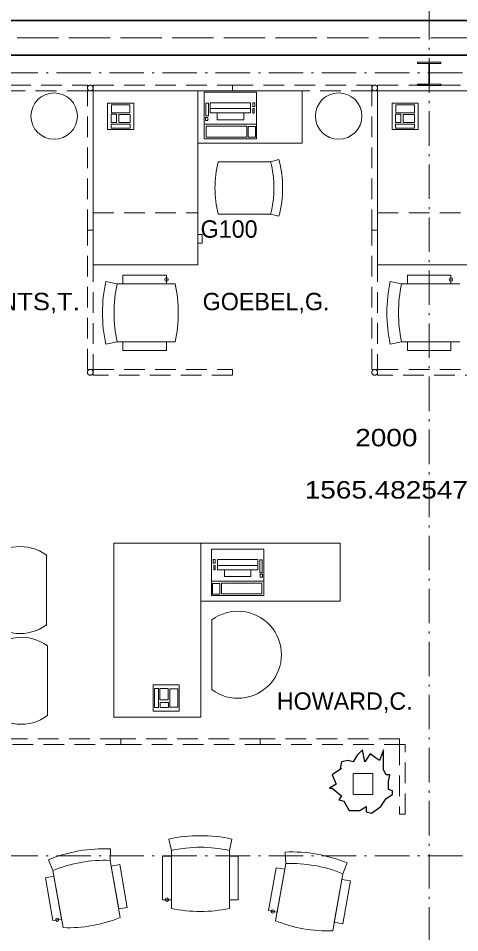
# Model space of a CAD drawing. Extents: x -118748 to -117136, y -118748 to -117596.
# Drawn here: x -117803.5 to -117681.9, y -118206 to -117953.8 of the extents above; entities that cross this region are included whole.
import ezdxf
from ezdxf.enums import TextEntityAlignment as Align

# ---------------------------------------------------------------- set-up
doc = ezdxf.new("R2010")
doc.units = 0
doc.header["$LTSCALE"] = 1.9
doc.header["$PDMODE"] = 32
doc.header["$PDSIZE"] = 0.95
for name, pattern in [('DOT_DASHED', [7.7, 5, -1.2, 0.3, -1.2]), ('LONG_DASHED', [7.5, 6, -1.5]), ('MEDIUM_DASHED', [4.5, 3, -1.5])]:
    doc.linetypes.add(name, pattern=pattern)
for name, color, linetype, lineweight in [('10', 7, 'DOT_DASHED', 13), ('12', 7, 'Continuous', 13), ('15', 7, 'Continuous', 13), ('16', 7, 'Continuous', 13), ('17', 7, 'Continuous', 25), ('20', 7, 'MEDIUM_DASHED', 13), ('23', 7, 'Continuous', 25), ('3', 7, 'Continuous', 35), ('30', 7, 'Continuous', 13), ('4', 7, 'Continuous', 35), ('45', 7, 'Continuous', 25), ('5', 7, 'Continuous', 13), ('6', 7, 'Continuous', 13), ('60', 7, 'LONG_DASHED', 13), ('9', 7, 'Continuous', 35)]:
    doc.layers.add(name, color=color, linetype=linetype, lineweight=lineweight)
doc.layers.add('53', color=7, linetype='Continuous')

msp = doc.modelspace()

# ---------------------------------------------------------------- linework, layer by layer
at = {"layer": '10'}
for p, q in [((-117690.321, -117628.339), (-117690.321, -118698.41)), ((-118641.571, -117968.81), (-117285.521, -117968.81)), ((-118641.571, -118184.81), (-117285.521, -118184.81))]:
    msp.add_line(p, q, dxfattribs=at)
at = {"layer": '12'}
msp.add_lwpolyline([(-117693.504, -117972.362), (-117687.088, -117972.362), (-117687.088, -117971.966), (-117690.172, -117971.966), (-117690.172, -117966.262), (-117687.088, -117966.262), (-117687.088, -117965.866), (-117693.504, -117965.866), (-117693.504, -117966.262), (-117690.42, -117966.262), (-117690.42, -117971.966), (-117693.504, -117971.966)], close=True, dxfattribs=at)
at = {"layer": '15', "lineweight": 25}
for p, q in [((-117459.921, -117954.41), (-117829.521, -117954.41)), ((-117469.521, -117964.01), (-117829.521, -117964.01))]:
    msp.add_line(p, q, dxfattribs=at)
at = {"layer": '15'}
for p, q in [((-117733.998, -117993.398), (-117731.676, -117992.791)), ((-117748.398, -117993.398), (-117733.998, -117993.398)), ((-117733.998, -118007.798), (-117748.398, -118007.798)), ((-117733.998, -118007.798), (-117731.676, -118008.404)), ((-117762.671, -118024.64), (-117774.671, -118024.64)), ((-117774.671, -118024.64), (-117774.671, -118027.04)), ((-117762.671, -118027.04), (-117762.671, -118024.64)), ((-117684.271, -118024.64), (-117696.271, -118024.64)), ((-117696.271, -118024.64), (-117696.271, -118027.04)), ((-117684.271, -118027.04), (-117684.271, -118024.64)), ((-117776.271, -118027.04), (-117779.399, -118026.364)), ((-117760.271, -118027.04), (-117776.271, -118027.04)), ((-117762.671, -118027.04), (-117774.671, -118027.04)), ((-117697.871, -118027.04), (-117700.999, -118026.364)), ((-117681.871, -118027.04), (-117697.871, -118027.04)), ((-117684.271, -118027.04), (-117696.271, -118027.04)), ((-117776.271, -118043.04), (-117779.399, -118043.716)), ((-117760.271, -118043.04), (-117776.271, -118043.04)), ((-117762.671, -118043.04), (-117774.671, -118043.04)), ((-117774.671, -118043.04), (-117774.671, -118045.44)), ((-117762.671, -118045.44), (-117762.671, -118043.04)), ((-117697.871, -118043.04), (-117700.999, -118043.716)), ((-117681.871, -118043.04), (-117697.871, -118043.04)), ((-117684.271, -118043.04), (-117696.271, -118043.04)), ((-117696.271, -118043.04), (-117696.271, -118045.44)), ((-117684.271, -118045.44), (-117684.271, -118043.04)), ((-117762.671, -118045.44), (-117774.671, -118045.44)), ((-117684.271, -118045.44), (-117696.271, -118045.44)), ((-117795.772, -118101.88), (-117795.772, -118121.08)), ((-117750.211, -118138.921), (-117750.211, -118119.721)), ((-117795.491, -118126.911), (-117795.491, -118146.111)), ((-117761.333, -118183.276), (-117762.009, -118180.149)), ((-117745.333, -118183.276), (-117744.657, -118180.149)), ((-117778.215, -118186.033), (-117778.092, -118182.835)), ((-117761.333, -118199.276), (-117761.333, -118183.276)), ((-117745.333, -118199.276), (-117745.333, -118183.276)), ((-117729.827, -118186.921), (-117729.95, -118183.724)), ((-117793.972, -118188.811), (-117795.181, -118185.848)), ((-117775.436, -118201.79), (-117778.215, -118186.033)), ((-117777.937, -118187.609), (-117775.573, -118187.192)), ((-117773.49, -118199.01), (-117775.573, -118187.192)), ((-117763.733, -118196.876), (-117763.733, -118184.876)), ((-117763.733, -118184.876), (-117761.333, -118184.876)), ((-117761.333, -118196.876), (-117761.333, -118184.876)), ((-117745.333, -118196.876), (-117745.333, -118184.876)), ((-117745.333, -118184.876), (-117742.933, -118184.876)), ((-117742.933, -118196.876), (-117742.933, -118184.876)), ((-117732.606, -118202.678), (-117729.827, -118186.921)), ((-117714.071, -118189.7), (-117712.861, -118186.737)), ((-117791.193, -118204.568), (-117793.972, -118188.811)), ((-117775.853, -118199.426), (-117777.937, -118187.609)), ((-117734.553, -118199.898), (-117732.469, -118188.08)), ((-117732.469, -118188.08), (-117730.105, -118188.497)), ((-117732.189, -118200.315), (-117730.105, -118188.497)), ((-117716.849, -118205.457), (-117714.071, -118189.7)), ((-117796.057, -118190.804), (-117793.694, -118190.387)), ((-117793.974, -118202.621), (-117796.057, -118190.804)), ((-117791.61, -118202.205), (-117793.694, -118190.387)), ((-117716.432, -118203.093), (-117714.348, -118191.275)), ((-117714.348, -118191.275), (-117711.985, -118191.692)), ((-117714.069, -118203.51), (-117711.985, -118191.692)), ((-117761.333, -118196.876), (-117763.733, -118196.876)), ((-117742.933, -118196.876), (-117745.333, -118196.876)), ((-117773.49, -118199.01), (-117775.853, -118199.426)), ((-117791.61, -118202.205), (-117793.974, -118202.621)), ((-117732.189, -118200.315), (-117734.553, -118199.898)), ((-117714.069, -118203.51), (-117716.432, -118203.093))]:
    msp.add_line(p, q, dxfattribs=at)
for points in [[(-117782.885, -118021.839), (-117754.085, -118021.839), (-117754.085, -117973.839), (-117782.885, -117973.839)], [(-117754.085, -117988.239), (-117725.285, -117988.239), (-117725.285, -117973.839), (-117754.085, -117973.839)], [(-117704.485, -118021.839), (-117675.685, -118021.839), (-117675.685, -117973.839), (-117704.485, -117973.839)], [(-117777.21, -118146.556), (-117777.21, -118098.556), (-117753.21, -118098.556), (-117753.21, -118146.556)], [(-117753.21, -118114.556), (-117753.21, -118098.556), (-117714.81, -118098.556), (-117714.81, -118114.556)]]:
    msp.add_lwpolyline(points, close=True, dxfattribs=at)
for centre, radius, start, end in [((-117761.548, -118000.597), 30.875, 345.35367, 14.64632), ((-117720.848, -118000.597), 28.475, 165.35367, 194.64632), ((-117761.548, -118000.597), 28.475, 345.35367, 14.64632), ((-117739.263, -118035.04), 41.063, 167.80217, 192.19782), ((-117739.263, -118035.04), 37.863, 167.80217, 192.19782), ((-117739.263, -118035.04), 37.863, 167.80217, 192.19782), ((-117797.279, -118035.04), 37.863, 347.80217, 12.19783), ((-117660.863, -118035.04), 41.063, 167.80217, 192.19782), ((-117660.863, -118035.04), 37.863, 167.80217, 192.19782), ((-117660.863, -118035.04), 37.863, 167.80217, 192.19782), ((-117802.972, -118111.48), 12, 53.1301, 306.86989), ((-117743.011, -118129.321), 12, 233.1301, 126.8699), ((-117802.691, -118136.511), 12, 53.1301, 306.86989), ((-117753.333, -118220.285), 41.063, 77.80217, 102.19783), ((-117779.667, -118223.868), 41.063, 87.80217, 112.19783), ((-117753.333, -118220.285), 37.863, 77.80217, 102.19783), ((-117753.333, -118220.285), 37.863, 77.80217, 102.19783), ((-117728.375, -118224.757), 41.063, 67.80217, 92.19783), ((-117779.667, -118223.868), 37.863, 87.80217, 112.19783), ((-117779.667, -118223.868), 37.863, 87.80217, 112.19783), ((-117728.375, -118224.757), 37.863, 67.80217, 92.19783), ((-117728.375, -118224.757), 37.863, 67.80217, 92.19783), ((-117753.333, -118162.268), 37.863, 257.80217, 282.19782), ((-117789.741, -118166.733), 37.863, 267.80217, 292.19783), ((-117718.301, -118167.621), 37.863, 247.80218, 272.19783)]:
    msp.add_arc(centre, radius, start, end, dxfattribs=at)
for p in [(-117762.671, -118025.84), (-117684.271, -118025.84), (-117762.533, -118196.876), (-117733.371, -118200.106), (-117792.792, -118202.413)]:
    msp.add_point(p, dxfattribs=at)
at = {"layer": '16'}
for p, q in [((-117752.287, -117983.025), (-117737.887, -117983.025)), ((-117735.829, -118109.006), (-117750.229, -118109.006))]:
    msp.add_line(p, q, dxfattribs=at)
for points in [[(-117752.287, -117987.025), (-117752.287, -117974.225), (-117737.887, -117974.225), (-117737.887, -117987.025)], [(-117771.7, -117984.461), (-117778.9, -117984.461), (-117778.9, -117977.261), (-117771.7, -117977.261)], [(-117777.865, -117979.842), (-117772.748, -117979.842), (-117772.748, -117977.637), (-117777.865, -117977.637)], [(-117751.83, -117980.742), (-117751.83, -117977.206), (-117751.122, -117977.206), (-117751.122, -117980.742)], [(-117750.623, -117978.704), (-117750.623, -117977.104), (-117739.514, -117977.104), (-117739.514, -117978.704)], [(-117738.89, -117977.123), (-117738.89, -117978.121), (-117738.307, -117978.121), (-117738.307, -117977.123)], [(-117693.3, -117984.461), (-117700.5, -117984.461), (-117700.5, -117977.261), (-117693.3, -117977.261)], [(-117699.465, -117979.842), (-117694.348, -117979.842), (-117694.348, -117977.637), (-117699.465, -117977.637)], [(-117777.948, -117982.505), (-117776.492, -117982.505), (-117776.492, -117980.216), (-117777.948, -117980.216)], [(-117775.827, -117982.588), (-117772.706, -117982.588), (-117772.706, -117980.299), (-117775.827, -117980.299)], [(-117750.623, -117979.91), (-117750.623, -117978.704), (-117739.514, -117978.704), (-117739.514, -117979.91)], [(-117748.709, -117981.783), (-117748.709, -117979.91), (-117741.386, -117979.91), (-117741.386, -117981.783)], [(-117738.89, -117978.704), (-117738.89, -117979.952), (-117738.474, -117979.952), (-117738.474, -117978.704)], [(-117699.549, -117982.505), (-117698.092, -117982.505), (-117698.092, -117980.216), (-117699.549, -117980.216)], [(-117697.427, -117982.588), (-117694.306, -117982.588), (-117694.306, -117980.299), (-117697.427, -117980.299)], [(-117751.913, -117981.99), (-117751.913, -117981.158), (-117751.247, -117981.158), (-117751.247, -117981.99)], [(-117772.706, -117983.004), (-117777.948, -117983.004), (-117777.948, -117984.086), (-117772.706, -117984.086)], [(-117751.746, -117983.572), (-117751.746, -117986.567), (-117740.554, -117986.567), (-117740.554, -117983.572)], [(-117740.138, -117983.655), (-117740.138, -117986.609), (-117738.141, -117986.609), (-117738.141, -117983.655)], [(-117694.306, -117983.004), (-117699.549, -117983.004), (-117699.549, -117984.086), (-117694.306, -117984.086)], [(-117735.829, -118113.006), (-117735.829, -118100.206), (-117750.229, -118100.206), (-117750.229, -118113.006)], [(-117749.227, -118103.104), (-117749.227, -118104.102), (-117749.809, -118104.102), (-117749.809, -118103.104)], [(-117737.494, -118104.685), (-117737.494, -118103.085), (-117748.603, -118103.085), (-117748.603, -118104.685)], [(-117736.287, -118106.724), (-117736.287, -118103.187), (-117736.994, -118103.187), (-117736.994, -118106.724)], [(-117749.227, -118104.685), (-117749.227, -118105.933), (-117749.643, -118105.933), (-117749.643, -118104.685)], [(-117737.494, -118105.891), (-117737.494, -118104.685), (-117748.603, -118104.685), (-117748.603, -118105.891)], [(-117739.408, -118107.764), (-117739.408, -118105.891), (-117746.73, -118105.891), (-117746.73, -118107.764)], [(-117736.204, -118107.972), (-117736.204, -118107.14), (-117736.87, -118107.14), (-117736.87, -118107.972)], [(-117747.979, -118109.636), (-117747.979, -118112.59), (-117749.976, -118112.59), (-117749.976, -118109.636)], [(-117736.37, -118109.553), (-117736.37, -118112.549), (-117747.562, -118112.549), (-117747.562, -118109.553)], [(-117766.352, -118137.661), (-117766.352, -118144.861), (-117759.152, -118144.861), (-117759.152, -118137.661)], [(-117764.896, -118138.667), (-117764.896, -118143.909), (-117765.977, -118143.909), (-117765.977, -118138.667)], [(-117764.48, -118141.787), (-117764.48, -118138.667), (-117762.191, -118138.667), (-117762.191, -118141.787)], [(-117761.734, -118143.826), (-117761.734, -118138.708), (-117759.528, -118138.708), (-117759.528, -118143.826)], [(-117764.396, -118143.909), (-117764.396, -118142.453), (-117762.108, -118142.453), (-117762.108, -118143.909)]]:
    msp.add_lwpolyline(points, close=True, dxfattribs=at)
at = {"layer": '17'}
msp.add_lwpolyline([(-117714.49, -118160.662), (-117717.024, -118162.472), (-117715.938, -118165.006), (-117717.749, -118166.092), (-117717.024, -118166.092), (-117714.49, -118168.264), (-117715.214, -118169.351), (-117713.766, -118169.713), (-117712.318, -118172.247), (-117709.422, -118172.247), (-117707.611, -118171.161), (-117707.611, -118172.609), (-117706.163, -118172.971), (-117703.629, -118171.161), (-117702.181, -118168.989), (-117700.371, -118167.902), (-117700.371, -118166.816), (-117701.457, -118166.454), (-117701.457, -118164.282), (-117701.095, -118162.472), (-117702.181, -118162.472), (-117702.905, -118161.024), (-117702.905, -118155.593), (-117703.991, -118158.489), (-117705.077, -118157.765), (-117706.525, -118156.679), (-117707.974, -118158.851), (-117708.698, -118155.593), (-117710.146, -118157.041), (-117711.232, -118158.851), (-117712.68, -118158.489), (-117714.49, -118158.851), (-117714.852, -118160.662)], dxfattribs=at)
at = {"layer": '17', "lineweight": 13}
msp.add_lwpolyline([(-117711.232, -118162.11), (-117711.232, -118167.902), (-117705.801, -118167.902), (-117705.801, -118162.11)], close=True, dxfattribs=at)
at = {"layer": '20'}
for points in [[(-117822.885, -117973.839), (-117822.885, -117972.239), (-117784.485, -117972.239), (-117784.485, -117973.839)], [(-117782.885, -117973.839), (-117782.885, -117972.239), (-117744.485, -117972.239), (-117744.485, -117973.839)], [(-117744.485, -117973.839), (-117744.485, -117972.239), (-117706.085, -117972.239), (-117706.085, -117973.839)], [(-117704.485, -117973.839), (-117704.485, -117972.239), (-117666.085, -117972.239), (-117666.085, -117973.839)], [(-117784.485, -117973.839), (-117782.885, -117973.839), (-117782.885, -118012.239), (-117784.485, -118012.239)], [(-117784.485, -117973.839), (-117782.885, -117973.839), (-117782.885, -118012.239), (-117784.485, -118012.239)], [(-117706.085, -117973.839), (-117704.485, -117973.839), (-117704.485, -118012.239), (-117706.085, -118012.239)], [(-117706.085, -117973.839), (-117704.485, -117973.839), (-117704.485, -118012.239), (-117706.085, -118012.239)], [(-117784.485, -118012.239), (-117782.885, -118012.239), (-117782.885, -118050.639), (-117784.485, -118050.639)], [(-117784.485, -118012.239), (-117782.885, -118012.239), (-117782.885, -118050.639), (-117784.485, -118050.639)], [(-117706.085, -118012.239), (-117704.485, -118012.239), (-117704.485, -118050.639), (-117706.085, -118050.639)], [(-117706.085, -118012.239), (-117704.485, -118012.239), (-117704.485, -118050.639), (-117706.085, -118050.639)], [(-117782.885, -118052.239), (-117782.885, -118050.639), (-117744.485, -118050.639), (-117744.485, -118052.239)], [(-117704.485, -118052.239), (-117704.485, -118050.639), (-117666.085, -118050.639), (-117666.085, -118052.239)], [(-117813.695, -118152.479), (-117813.695, -118154.079), (-117775.295, -118154.079), (-117775.295, -118152.479)], [(-117775.295, -118152.479), (-117775.295, -118154.079), (-117736.895, -118154.079), (-117736.895, -118152.479)], [(-117736.895, -118152.479), (-117736.895, -118154.079), (-117698.495, -118154.079), (-117698.495, -118152.479)], [(-117696.895, -118154.079), (-117698.495, -118154.079), (-117698.495, -118173.279), (-117696.895, -118173.279)]]:
    msp.add_lwpolyline(points, close=True, dxfattribs=at)
for centre in [(-117783.685, -117973.039), (-117783.685, -117973.039), (-117705.285, -117973.039), (-117705.285, -117973.039), (-117783.685, -118051.439), (-117705.285, -118051.439)]:
    msp.add_circle(centre, 0.8, dxfattribs=at)
at = {"layer": '23', "linetype": 'MEDIUM_DASHED', "lineweight": 13}
for points in [[(-117754.085, -118021.839), (-117782.885, -118021.839), (-117782.885, -118007.439), (-117754.085, -118007.439)], [(-117675.685, -118021.839), (-117704.485, -118021.839), (-117704.485, -118007.439), (-117675.685, -118007.439)], [(-117754.085, -118015.839), (-117752.885, -118015.839), (-117752.885, -118013.439), (-117754.085, -118013.439)]]:
    msp.add_lwpolyline(points, close=True, dxfattribs=at)
at = {"layer": '3'}
msp.add_lwpolyline([(-118098.321, -117954.41), (-117829.521, -117954.41), (-117459.921, -117954.41), (-117459.921, -118170.41), (-117370.321, -118170.41), (-117370.321, -118352.81), (-117459.921, -118352.81), (-117459.921, -118645.61), (-117704.721, -118645.61), (-117704.721, -118592.81), (-117847.121, -118592.81), (-117850.321, -118592.801), (-117860.744, -118590.984), (-117862.249, -118590.443), (-117871.571, -118585.668), (-117872.847, -118584.703), (-117880.323, -118577.368), (-117881.254, -118576.067), (-117886.205, -118566.837), (-117886.706, -118565.318), (-117888.682, -118555.032), (-117888.707, -118553.433), (-117890.316, -118553.433)], dxfattribs=at)
at = {"layer": '30'}
for centre in [(-117793.635, -117980.776), (-117715.235, -117980.776)]:
    msp.add_circle(centre, 6.4, dxfattribs=at)
at = {"layer": '4'}
msp.add_lwpolyline([(-118496.721, -117964.01), (-118496.721, -118636.01), (-118271.121, -118636.01), (-118271.121, -118588.01), (-118115.969, -118588.01), (-118106.1, -118586.234), (-118096.66, -118581.314), (-118089.115, -118573.804), (-118084.156, -118564.399), (-118081.154, -118548.633), (-118079.134, -118548.633), (-117884.057, -118548.587), (-117881.646, -118565.336), (-117876.897, -118574.111), (-117869.271, -118581.538), (-117859.789, -118586.351), (-117850.271, -118588.01), (-117695.121, -118588.01), (-117695.121, -118636.01), (-117469.521, -118636.01), (-117469.521, -117964.01)], close=True, dxfattribs=at)
at = {"layer": '5'}
for points in [[(-117981.521, -118118.36), (-117981.521, -117964.01), (-117469.521, -117964.01), (-117469.521, -117992.81), (-117469.521, -118180.01), (-117469.521, -118292.01), (-117839.871, -118292.01), (-117839.871, -118184.81)], [(-117979.078, -117964.01), (-117469.521, -117964.01), (-117469.521, -118636.01), (-117695.121, -118636.01), (-117695.121, -118588.01), (-117850.271, -118588.01)]]:
    msp.add_lwpolyline(points, dxfattribs=at)
at = {"layer": '6'}
msp.add_lwpolyline([(-117981.521, -117964.01), (-117469.521, -117964.01), (-117469.521, -118292.01), (-117839.871, -118292.01), (-117839.871, -118184.81)], dxfattribs=at)
at = {"layer": '60'}
msp.add_lwpolyline([(-117464.721, -118175.21), (-117464.721, -117959.21), (-118501.521, -117959.21)], dxfattribs=at)

# ---------------------------------------------------------------- texts
at = {"layer": '45', "width": 1.2}
for s, p in [('2000', (-117702.092, -118071.848)), ('1565.482547', (-117702.092, -118086.248))]:
    msp.add_text(s, height=4.8, dxfattribs=at).set_placement(p, align=Align.CENTER)
at = {"layer": '53', "width": 1.1}
msp.add_text('CLEMENTS,T.', height=4.8, dxfattribs=at).set_placement((-117833.238, -118034.323))
at = {"layer": '53'}
for s, p in [('GOEBEL,G.', (-117752.714, -118034.323)), ('HOWARD,C.', (-117732.279, -118144.507))]:
    msp.add_text(s, height=4.8, dxfattribs=at).set_placement(p)
at = {"layer": '9'}
msp.add_text('G100', height=4.8, dxfattribs=at).set_placement((-117745.432, -118014.325), align=Align.CENTER)

doc.saveas('drawing.dxf')
